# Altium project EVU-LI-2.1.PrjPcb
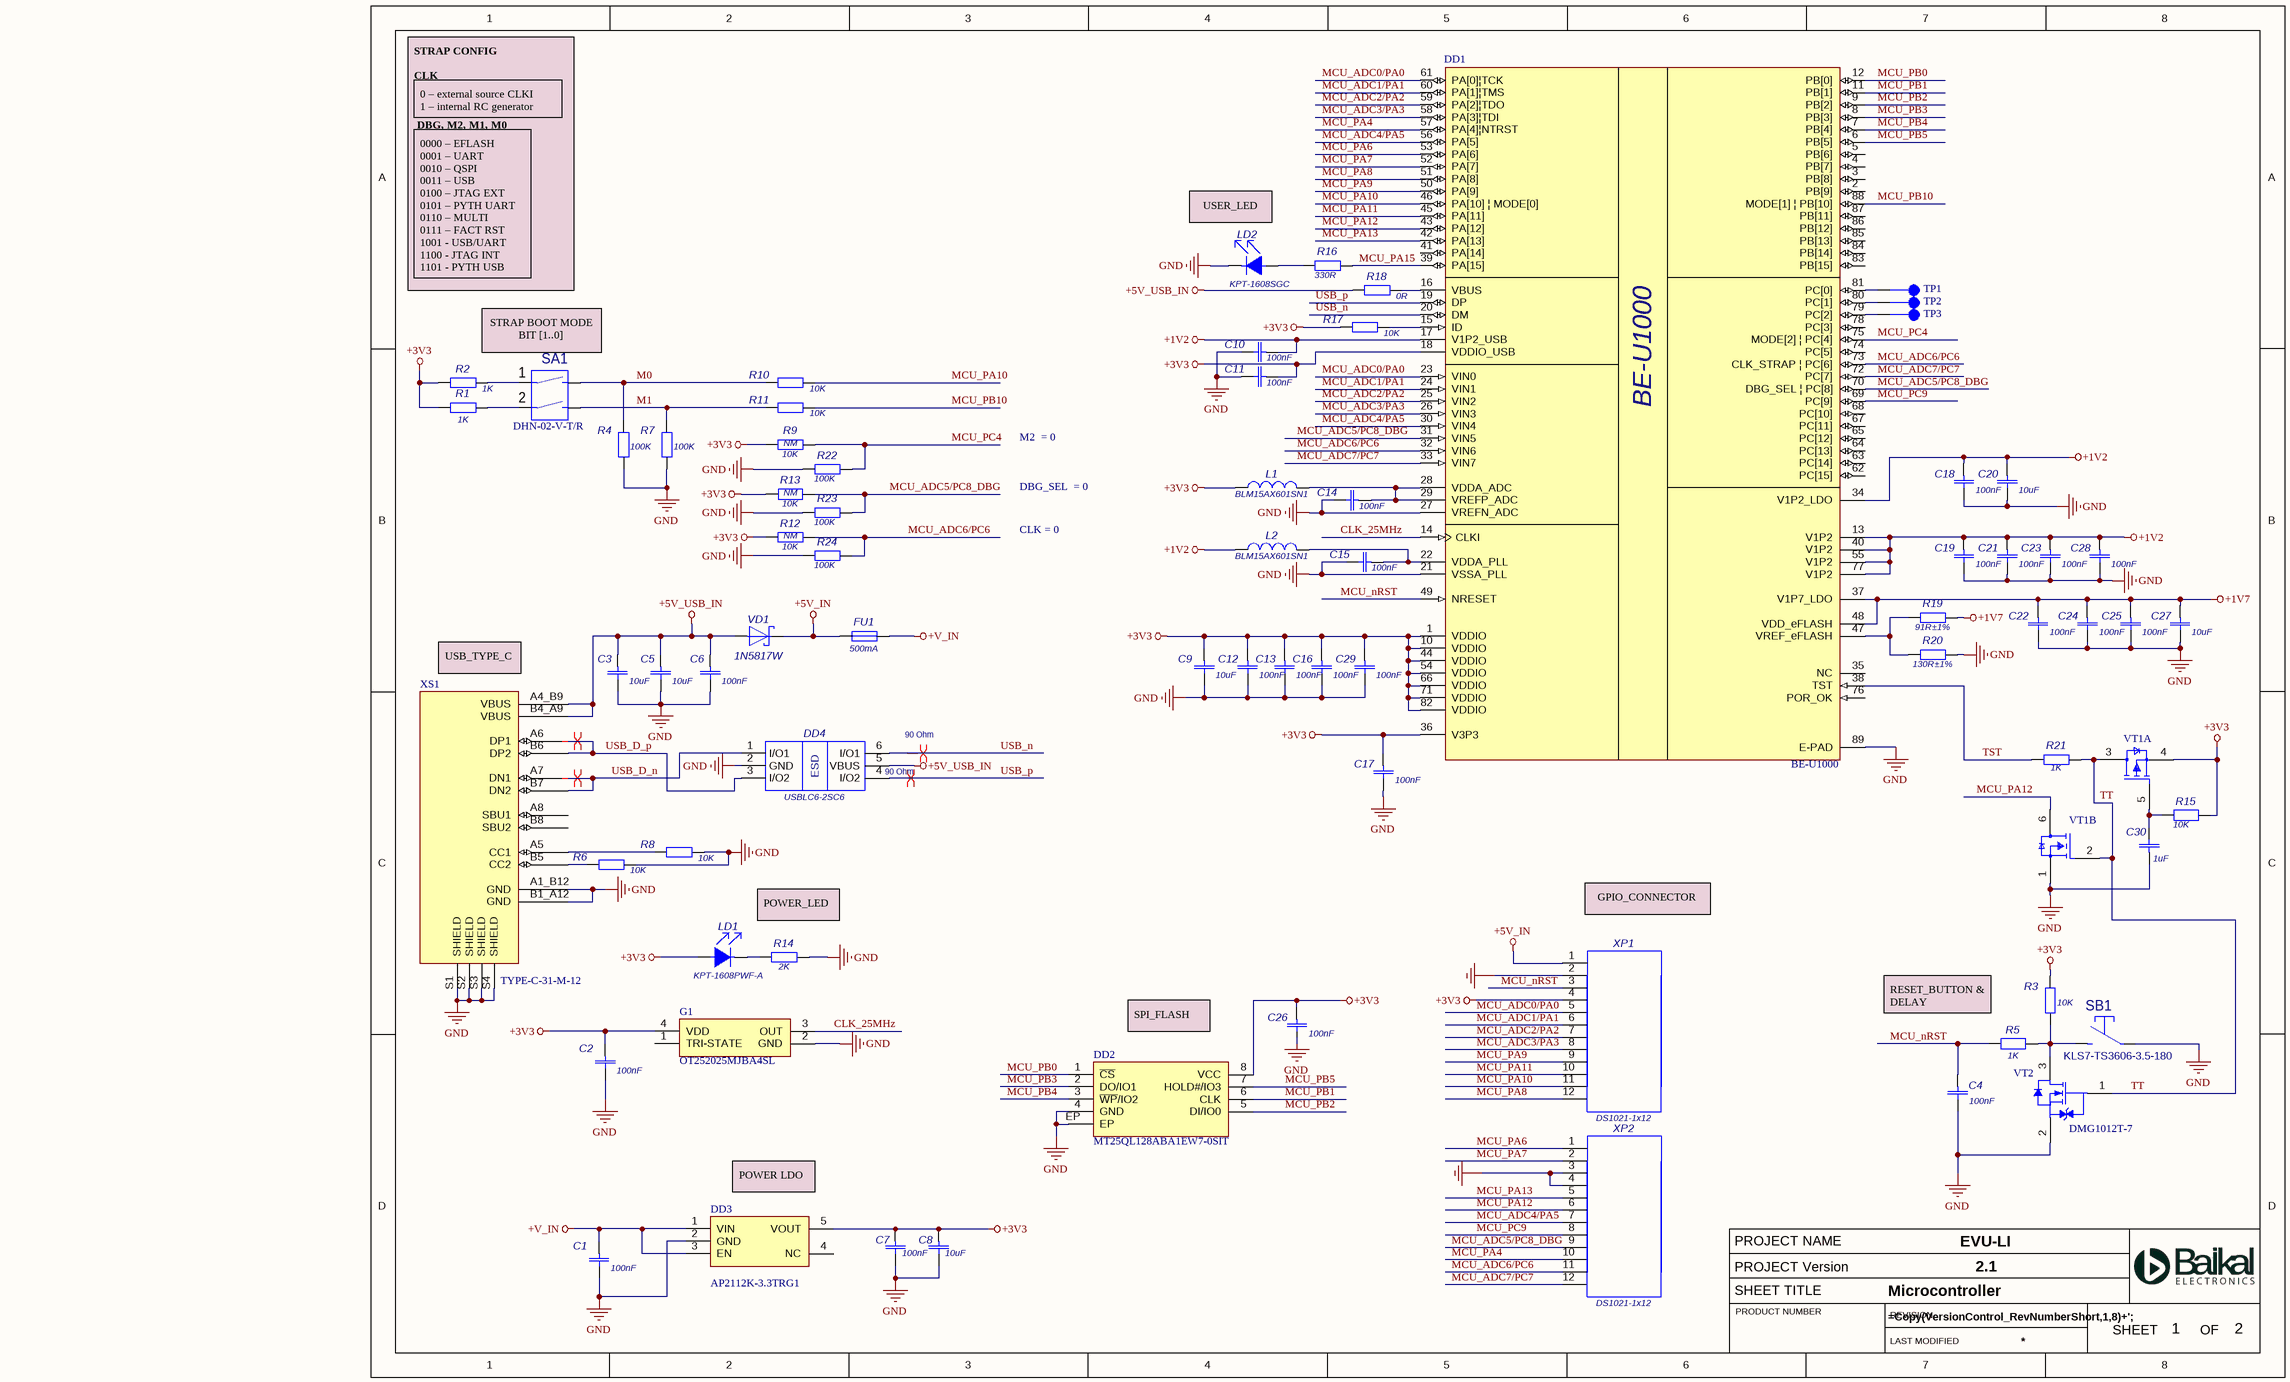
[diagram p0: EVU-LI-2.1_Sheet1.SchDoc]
2 sheets, 75 parts. Net scope: global (net labels, ports and power ports of the same name join across sheets).
Board file: PCB_EVU-LI_2.1.PcbDoc
Sheets:
  EVU-LI-2.1_Sheet1.SchDoc
  EVU-LI-2.1_Sheet2.SchDoc

## Sheet EVU-LI-2.1_Sheet1.SchDoc: EVU-LI-2.1
size A3; SheetNumber: 1; SheetTotal: 2; Prj: EVU-LI; Ver: 2.1; Ti: Microcontroller

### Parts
C1  value 100nF  [CAPC1005X50N]  (hidden comment: GRM155R71C104KA88D)
C2  value 100nF  [CAPC1005X50N]  (hidden comment: GRM155R71C104KA88D)
C3  value 10uF  [CAPC2012X125N]  (hidden comment: GRM21BR61C106KE15L)
C4  value 100nF  [CAPC1005X50N]  (hidden comment: GRM155R71C104KA88D)
C5  value 10uF  [CAPC2012X125N]  (hidden comment: GRM21BR61C106KE15L)
C6  value 100nF  [CAPC1005X50N]  (hidden comment: GRM155R71C104KA88D)
C7  value 100nF  [CAPC1005X50N]  (hidden comment: GRM155R71C104KA88D)
C8  value 10uF  [CAPC2012X125N]  (hidden comment: GRM21BR61C106KE15L)
C9  value 10uF  [CAPC2012X125N]  (hidden comment: GRM21BR61C106KE15L)
C10  value 100nF  [CAPC1005X50N]  (hidden comment: GRM155R71C104KA88D)
C11  value 100nF  [CAPC1005X50N]  (hidden comment: GRM155R71C104KA88D)
C12  value 100nF  [CAPC1005X50N]  (hidden comment: GRM155R71C104KA88D)
C13  value 100nF  [CAPC1005X50N]  (hidden comment: GRM155R71C104KA88D)
C14  value 100nF  [CAPC1005X50N]  (hidden comment: GRM155R71C104KA88D)
C15  value 100nF  [CAPC1005X50N]  (hidden comment: GRM155R71C104KA88D)
C16  value 100nF  [CAPC1005X50N]  (hidden comment: GRM155R71C104KA88D)
C17  value 100nF  [CAPC1005X50N]  (hidden comment: GRM155R71C104KA88D)
C18  value 100nF  [CAPC1005X50N]  (hidden comment: GRM155R71C104KA88D)
C19  value 100nF  [CAPC1005X50N]  (hidden comment: GRM155R71C104KA88D)
C20  value 10uF  [CAPC2012X125N]  (hidden comment: GRM21BR61C106KE15L)
C21  value 100nF  [CAPC1005X50N]  (hidden comment: GRM155R71C104KA88D)
C22  value 100nF  [CAPC1005X50N]  (hidden comment: GRM155R71C104KA88D)
C23  value 100nF  [CAPC1005X50N]  (hidden comment: GRM155R71C104KA88D)
C24  value 100nF  [CAPC1005X50N]  (hidden comment: GRM155R71C104KA88D)
C25  value 100nF  [CAPC1005X50N]  (hidden comment: GRM155R71C104KA88D)
C26  value 100nF  [CAPC1005X50N]  (hidden comment: GRM155R71C104KA88D)
C27  value 10uF  [CAPC2012X125N]  (hidden comment: GRM21BR61C106KE15L)
C28  value 100nF  [CAPC1005X50N]  (hidden comment: GRM155R71C104KA88D)
C29  value 100nF  [CAPC1005X50N]  (hidden comment: GRM155R71C104KA88D)
C30  value 1uF  [CAPC1005X50N]  (hidden comment: GRM155Z71A105KE01D)
DD1  BE-U1000  [QFNWB10X10-88L-AL]
DD2  MT25QL128ABA1EW7-0SIT  [W-PDFN-8(5x6)]
DD3  AP2112K-3.3TRG1  [SOT95P285X140-5N]
DD4  USBLC6-2SC6  [SOT95P280X145-6N]
FU1  value 500mA  [RESC1608X45N]  (hidden comment: JFC0603-0500FS)
G1  OT252025MJBA4SL  [Crystal_4-SMD_2.5x2.0]
L1  BLM15AX601SN1  [BLM15X10X05X50N]
L2  BLM15AX601SN1  [BLM15X10X05X50N]
LD1  KPT-1608PWF-A  [KPT1608X16X08X75N_LINE]
LD2  KPT-1608SGC  [KPT1608X16X08X75N_LINE]
R1  value 1K  [RESC1005X35N]  (hidden comment: RC0402FR-071KL)
R2  value 1K  [RESC1005X35N]  (hidden comment: RC0402FR-071KL)
R3  value 10K  [RESC1005X35N]  (hidden comment: RC0402FR-0710KL)
R4  value 100K  [RESC1005X35N]  (hidden comment: RC0402FR-07100KL)
R5  value 1K  [RESC1005X35N]  (hidden comment: RC0402FR-071KL)
R6  value 10K  [RESC1005X35N]  (hidden comment: RC0402FR-0710KL)
R7  value 100K  [RESC1005X35N]  (hidden comment: RC0402FR-07100KL)
R8  value 10K  [RESC1005X35N]  (hidden comment: RC0402FR-0710KL)
R9  value 10K  DNP: NM  [RESC1005X35N]  (hidden comment: RC0402FR-0710KL)
R10  value 10K  [RESC1005X35N]  (hidden comment: RC0402FR-0710KL)
R11  value 10K  [RESC1005X35N]  (hidden comment: RC0402FR-0710KL)
R12  value 10K  DNP: NM  [RESC1005X35N]  (hidden comment: RC0402FR-0710KL)
R13  value 10K  DNP: NM  [RESC1005X35N]  (hidden comment: RC0402FR-0710KL)
R14  value 2K  [RESC1005X35N]  (hidden comment: CR0402-JW-202-G)
R15  value 10K  [RESC1005X35N]  (hidden comment: RC0402FR-0710KL)
R16  value 330R  [RESC1005X35N]  (hidden comment: CR0402-JW-331-G)
R17  value 10K  [RESC1005X35N]  (hidden comment: RC0402FR-0710KL)
R18  value 0R  [RESC1005X35N]  (hidden comment: RC0402FR-070RL)
R19  value 91R  Tolerance: ±1%  [RESC1005X35N]  (hidden comment: RC0402FR-0791RL)
R20  value 130R  Tolerance: ±1%  [RESC1005X35N]  (hidden comment: RC0402FR-07130RL)
R21  value 1K  [RESC1005X35N]  (hidden comment: RC0402FR-071KL)
R22  value 100K  [RESC1005X35N]  (hidden comment: RC0402FR-07100KL)
R23  value 100K  [RESC1005X35N]  (hidden comment: RC0402FR-07100KL)
R24  value 100K  [RESC1005X35N]  (hidden comment: RC0402FR-07100KL)
SA1  DHN-02-V-T/R  [A6H-21]
SB1  KLS7-TS3606-3.5-180  [KLS7-TS3606-3.5-180]
TP1  (no value)  [PIN_0.7x0.7]  (no BOM)
TP2  (no value)  [PIN_0.7x0.7]  (no BOM)
TP3  (no value)  [PIN_0.7x0.7]  (no BOM)
VD1  1N5817W  [DIOD_SOD-123]
VT1  BSS8402DW-7-F  [FP-SOT363-MFG]  (value not drawn)  (parts A,B of 2)
VT2  DMG1012T-7  [DIOD-SOT523-3_V]
XP1  DS1021-1x12  [PLS-12]
XP2  DS1021-1x12  [PLS-12]
XS1  TYPE-C-31-M-12  [TYPE-C-31-M-12]

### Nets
+1V2: C10.2 C18.2 C19.2 C20.2 C21.2 C23.2 C28.2 DD1.13(V1P2) DD1.17(V1P2_USB) DD1.34(V1P2_LDO) DD1.40(V1P2) DD1.55(V1P2) DD1.77(V1P2) L2.1
+1V7: C22.2 C24.2 C25.2 C27.2 DD1.37(V1P7_LDO) DD1.48(VDD_eFLASH) R19.2
+3V3: C2.2 C7.2 C8.2 C9.2 C11.2 C12.2 C13.2 C16.2 C17.2 C26.2 C29.2 DD1.1(VDDIO) DD1.10(VDDIO) DD1.18(VDDIO_USB) DD1.36(V3P3) DD1.44(VDDIO) DD1.54(VDDIO) DD1.66(VDDIO) DD1.71(VDDIO) DD1.82(VDDIO) DD2.8(VCC) DD3.5(VOUT) G1.4(VDD) L1.1 LD1.1 R1.1 R2.1 R3.2 R9.1 R12.1 R13.2 R15.1 R17.1 VT1.4(S2) XP1.4
+5V_IN: FU1.1 VD1.C XP1.1
+5V_USB_IN: C3.2 C5.2 C6.2 DD4.5(VBUS) R18.1 VD1.A XS1.A4_B9(VBUS) XS1.B4_A9(VBUS)
+V_IN: C1.2 DD3.1(VIN) DD3.3(EN) FU1.2
GND: C1.1 C2.1 C3.1 C4.1 C5.1 C6.1 C7.1 C8.1 C9.1 C10.1 C11.1 C12.1 C13.1 C14.1 C15.1 C16.1 C17.1 C18.1 C19.1 C20.1 C21.1 C22.1 C23.1 C24.1 C25.1 C26.1 C27.1 C28.1 C29.1 C30.2 DD1.21(VSSA_PLL) DD1.27(VREFN_ADC) DD1.89(E-PAD) DD2.4(GND) DD2.EP DD3.2(GND) DD4.2(GND) G1.2(GND) LD2.2 R4.1 R6.2 R7.1 R8.2 R14.2 R20.2 R22.1 R23.1 R24.1 SB1.1 VT1.1(S1) VT2.2(S) XP1.2 XP2.3 XP2.4 XS1.A1_B12(GND) XS1.B1_A12(GND) XS1.S1(SHIELD) XS1.S2(SHIELD) XS1.S3(SHIELD) XS1.S4(SHIELD)
CLK_25MHz: DD1.14(CLKI) G1.3(OUT)
M0: R4.2 R10.1 SA1.11
M1: R7.2 R11.1 SA1.22
MCU_ADC0/PA0: DD1.23(VIN0) DD1.61(PA[0]¦TCK) XP1.5
MCU_ADC1/PA1: DD1.24(VIN1) DD1.60(PA[1]¦TMS) XP1.6
MCU_ADC2/PA2: DD1.25(VIN2) DD1.59(PA[2]¦TDO) XP1.7
MCU_ADC3/PA3: DD1.26(VIN3) DD1.58(PA[3]¦TDI) XP1.8
MCU_ADC4/PA5: DD1.30(VIN4) DD1.56(PA[5]) XP2.7
MCU_ADC5/PC8_DBG: DD1.31(VIN5) DD1.70(DBG_SEL_¦_PC[8]) R13.1 R23.2 XP2.9
MCU_ADC6/PC6: DD1.32(VIN6) DD1.73(CLK_STRAP_¦_PC[6]) R12.2 R24.2 XP2.11
MCU_ADC7/PC7: DD1.33(VIN7) DD1.72(PC[7]) XP2.12
MCU_nRST: C4.2 DD1.49(NRESET) R5.2 XP1.3
MCU_PA4: DD1.57(PA[4]¦NTRST) XP2.10
MCU_PA6: DD1.53(PA[6]) XP2.1
MCU_PA7: DD1.52(PA[7]) XP2.2
MCU_PA8: DD1.51(PA[8]) XP1.12
MCU_PA9: DD1.50(PA[9]) XP1.9
MCU_PA10: DD1.46(PA[10]_¦_MODE[0]) R10.2 XP1.11
MCU_PA11: DD1.45(PA[11]) XP1.10
MCU_PA12: DD1.43(PA[12]) VT1.6(D1) XP2.6
MCU_PA13: DD1.42(PA[13]) XP2.5
MCU_PA15: DD1.39(PA[15]) R16.2
MCU_PB0: DD1.12(PB[0]) DD2.1(~{CS})
MCU_PB1: DD1.11(PB[1]) DD2.6(CLK)
MCU_PB2: DD1.9(PB[2]) DD2.5(DI/IO0)
MCU_PB3: DD1.8(PB[3]) DD2.2(DO/IO1)
MCU_PB4: DD1.7(PB[4]) DD2.3(~{WP}/IO2)
MCU_PB5: DD1.6(PB[5]) DD2.7(HOLD#/IO3)
MCU_PB10: DD1.88(MODE[1]_¦_PB[10]) R11.2
MCU_PC4: DD1.75(MODE[2]_¦_PC[4]) R9.2 R22.2
MCU_PC9: DD1.69(PC[9]) XP2.8
TST: DD1.38(TST) R21.1
TT: R21.2 VT1.2(G1) VT1.3(D2) VT2.1(G)
USB_D_n: DD4.1(I/O1) XS1.A7(DN1) XS1.B7(DN2)
USB_D_p: DD4.3(I/O2) XS1.A6(DP1) XS1.B6(DP2)
USB_n: DD1.20(DM) DD4.6(I/O1)
USB_p: DD1.19(DP) DD4.4(I/O2)
NetC14_2: C14.2 DD1.28(VDDA_ADC) DD1.29(VREFP_ADC) L1.2
NetC15_2: C15.2 DD1.22(VDDA_PLL) L2.2
NetC30_1: C30.1 R15.2 VT1.5(G2)
NetDD1_15: DD1.15(ID) R17.2
NetDD1_16: DD1.16(VBUS) R18.2
NetDD1_47: DD1.47(VREF_eFLASH) R19.1 R20.1
NetDD1_79: DD1.79(PC[2]) TP2.1
NetDD1_80: DD1.80(PC[1]) TP3.1
NetDD1_81: DD1.81(PC[0]) TP1.1
NetLD1_2: LD1.2 R14.1
NetLD2_1: LD2.1 R16.1
NetR1_2: R1.2 SA1.2
NetR2_2: R2.2 SA1.1
NetR3_1: R3.1 R5.1 SB1.2 VT2.3(D)
NetR6_1: R6.1 XS1.B5(CC2)
NetR8_1: R8.1 XS1.A5(CC1)

Not connected (* = marked no-connect by the designer): DD1 2(PB[9]) 3(PB[8]) 4(PB[7]) 5(PB[6]) 35(NC) 41(PA[14]) 62(PC[15]) 63(PC[14]) 64(PC[13]) 65(PC[12]) 67(PC[11]) 68(PC[10]) 74(PC[5]) 76(POR_OK) 78(PC[3]) 83(PB[15]) 84(PB[14]) 85(PB[13]) 86(PB[12]) 87(PB[11]); DD3 4(NC); G1 1(TRI-STATE); XS1 A8(SBU1) B8(SBU2)

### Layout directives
differential pair: (no net found under the mark)
differential pair; USB_HS_90: 90 Ohm; differential pair class 90 Ohm: USB_n, USB_p

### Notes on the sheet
- 0 – external source CLKI
  1 – internal RC generator
- USER_LED
- STRAP CONFIG
  CLK
  DBG, M2, M1, M0
- 0000 – EFLASH
  0001 – UART
  0010 – QSPI
  0011 – USB
  0100 – JTAG EXT
  0101 – PYTH UART
  0110 – MULTI
  0111 – FACT RST
  1001 - USB/UART
  1100 - JTAG INT
  1101 - PYTH USB
- STRAP BOOT MODE BIT [1..0]
- M2  = 0
- DBG_SEL  = 0
- CLK = 0
- (near XS1) USB_TYPE_C
- GPIO_CONNECTOR
- POWER_LED
- (near DD2) SPI_FLASH
- (near R5) RESET_BUTTON & DELAY
- (near DD3) POWER LDO

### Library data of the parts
C1 C2 C4 C6 C7 C10-C19 C21-C26 C28 C29 = GRM155R71C104KA88D: 0402 X7R  0,1 uF±10% 16V; Manufacturer: "Murata"; Tolerance: ±10%; Power_Voltage: 16В; NOM: 0402 X7R 100nF ±10% 16В; Value Ru: 0,1 мкФ
C3 C5 C8 C9 C20 C27 = GRM21BR61C106KE15L: 0805 X5R 10uF±10% 16V; Manufacturer: "Murata"; Tolerance: ±10%; Value Ru: 10 мкФ
C30 = GRM155Z71A105KE01D: 0402 X7R  1 uF±10% 10V; Manufacturer: "Murata"; Tolerance: ±10%; Power_Voltage: 10В; NOM: 0402 X7R 1uF ±10% 10В; Value Ru: 1 мкФ
DD1 = BE-U1000: Microcontroller BE-U1000; Manufacturer: "Baikal Electronics"; TKE: QFN 88
DD2 = MT25QL128ABA1EW7-0SIT: FLASH 128MBIT SPI 8WPDFN; Manufacturer: "Micron"
DD3 = AP2112K-3.3TRG1: LDO voltage regulator; Manufacturer_Name: Diodes Incorporated; Manufacturer: "Diodes"
DD4 = USBLC6-2SC6: Very low capacitance ESD protector; Manufacturer: "STMicroelectronics"; MARK: UL26
FU1 = JFC0603-0500FS: Fuse 500mA 32V 0603; Manufacturer: "JDT Fuse Industrial"; MARK: F
G1 = OT252025MJBA4SL: 3.3V ±10ppm 5mA ±20ppm CMOS 25MHz  Oscillator; Manufacturer: "YXC"; Manufacturer_Part_Number: OT322525MJBA4SL; TKE: SMD3225-4P
L1 L2 = BLM15AX601SN1: 600 Ohms/100MHz 0,5A 0,34 Ohms; Manufacturer: "Murata"; Value: 600 Ом/100MГц 0,5A 0,34 Ом
LD1 = KPT-1608PWF-A: 0603 LED Diod SMD White; Manufacturer: "Kingbright"; TKE: 0603
LD2 = KPT-1608SGC: 0603 LED Diod SMD Green; Manufacturer: "Kingbright"; TKE: 0603
R1 R2 R5 = RC0402FR-071KL: 0402 1 kOhm ±1% 0.063W; Manufacturer: "Yageo"; Power_Voltage: 0,0625 W; MARK: 102; TKE: 0402; NOM: 0402 1K ±1% 0,0625 W; Value Ru: 1 кОм
R3 R6 R8-R13 R17 = RC0402FR-0710KL: 0402 10 kOhm ±1% 0.063W; Manufacturer: "Yageo"; Power_Voltage: 0,0625 W; MARK: 103; TKE: 0402; NOM: 0402 10K ±1% 0,0625 W; Value Ru: 10 кОм
R4 R7 R22-R24 = RC0402FR-07100KL: 0402 100 kOhm ±1% 0.063W; Manufacturer: "Yageo"; Power_Voltage: 0,0625 W; MARK: 103; TKE: 0402; NOM: 0402 100K ±1% 0,0625 W; Value Ru: 100 кОм
R14 = CR0402-JW-202-G: 0402 2 kOhm±5% 0.063W; Manufacturer: "Bourns"; Power_Voltage: 0,0625 W; MARK: 202; TKE: 0402; NOM: 0402 2K ±5% 0,0625 W; Tolerance: ±5%; Value Ru: 2 кОм
R15 = RC0402FR-0710KL: 0402 10 kOhm ±1% 0.063W; Manufacturer: "Yageo"; TKE: 0402; MARK: 103; Power_Voltage: 0,0625 W; NOM: 0402 10K ±1% 0,0625 W; Value Ru: 10 кОм
R16 = CR0402-JW-331-G: 0402 330 Ohm±5% 0.063W; Manufacturer: "Bourns"; Power_Voltage: 0,0625 W; MARK: 331; TKE: 0402; NOM: 0402 330R ±5% 0,0625 W; Tolerance: ±5%; Value Ru: 330 Ом
R18 = RC0402FR-070RL: 0402 0 Ohm ±1% 0.063W; Manufacturer: "Yageo"; Power_Voltage: 0,0625 W; MARK: 000; TKE: 0402; NOM: 0402 0R ±1% 0,0625 W; Value Ru: 0 Ом
R19 = RC0402FR-0791RL: 0402 91 Ohm ±1% 0.063W; Manufacturer: "Yageo"; Power_Voltage: 0,0625 W; MARK: 102; TKE: 0402; NOM: 0402 91R ±1% 0,0625 W; Value Ru: 91 Ом
R20 = RC0402FR-07130RL: 0402 130 Ohm ±1% 0.063W; Manufacturer: "Yageo"; Power_Voltage: 0,0625 W; MARK: 102; TKE: 0402; NOM: 0402 130R ±1% 0,0625 W; Value Ru: 130 Ом
R21 = RC0402FR-071KL: 0402 1 kOhm ±1% 0.063W; Manufacturer: "Yageo"; TKE: 0402; MARK: 102; Power_Voltage: 0,0625 W; NOM: 0402 1K ±1% 0,0625 W; Value Ru: 1 кОм
SA1 = DHN-02-V-T/R: 2 switches in case; Manufacturer: "DIPTRONICS"; ESKDname: Переключатель DHN-02-V-T/R
SB1 = KLS7-TS3606-3.5-180: Kind of Tactile Switch; Manufacturer: "KLS"; ESKDname: Кнопка тактовая KLS7-TS3606-3.5-180
TP1-TP3 = TP: Contacts, Test points and mounting hole pin
VD1 = 1N5817W: Diode Schottky 20V 1A [SOD-123]; Manufacturer: HOTTECH ELECTRONICS; ESKDname: * 1N5817W, *
VT1 = BSS8402DW-7-F: MOSFET N/P-CH 60V/50V SC70-6; Manufacturer: Diodes; Drain To Source Voltage: 60/-50V; Threshold Vgs Max: 2.5/-2V; Number Of Channels: 2; Turn On Delay Time: 7/10ns; Turn Off Delay Time: 11/18ns; Depletion Mode: False; Number Of P Channels: 1; Transconductance: 0.08/0.05S; Rthja Max: 625°C/W; Gate To Source Voltage: 20V; Power Dissipation: 200mW; Drain To Source Resistance: 4.4/10Ω; Continuous Drain Current: 115/-130mA; Threshold Vgs Min: 1/-0.8V; Max Junction Temp: +150°C; Automotive Grade: NA; Drain To Source Breakdown Voltage: 70/-50V; Standoff Height: 0mm; Pulse Drain Current: 800mA
VT2 = DMG1012T-7: N-Channel Enhancement Mode MOSFET, 20 V, 630 mA, -55 to 150 degC, 3-Pin SOT23, RoHS, Tape and Reel; Manufacturer: Diodes Inc; Continuous Drain Current (ID): 630mA; Number of Channels: 1; Drain to Source Voltage (Vdss): 20V; Gate to Source Voltage (Vgs): 6V; Turn-On Delay Time: 5.1ns; Rds On Max: 400mOhm; Power Dissipation: 280mW; Fall Time: 12.3ns; Input Capacitance: 60.67pF; Turn-Off Delay Time: 26.7ns; Rise Time: 7.4ns; Drain to Source Resistance: 300mOhm; Element Configuration: Single; Case\/Package: SOT-523; Threshold Voltage: 1V
XP1 XP2 = DS1021-1x12: Connector 2.54 pitch, 1 rows, 8.54 height; ManufacturerPartNumber: DS1021-1x12 (PLS-12); Manufacturer: "Connfly"
XS1 = TYPE-C-31-M-12: USB TYPE-C 5A 16P Female SMD USB Connectors; Manufacturer: "GCT"; MP: USB4800-03-A; MF: Global Connector Technology

## Sheet EVU-LI-2.1_Sheet2.SchDoc
size A3; SheetNumber: 2; SheetTotal: 2; Prj: EVU-LI; Ver: 2.1; Ti: Revision History
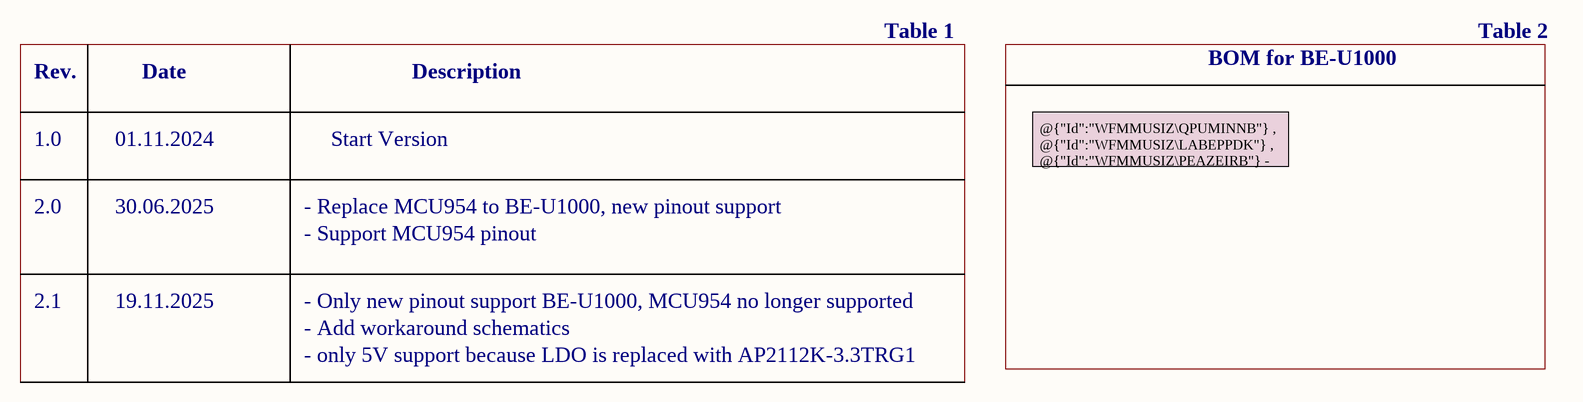
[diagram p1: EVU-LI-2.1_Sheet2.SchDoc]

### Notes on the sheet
- Table 1
- BOM for BE-U1000
- Table 2
- Rev.
- Date
- Description
- 1.0
- 01.11.2024
- Start Version
- @{"Id":"WFMMUSIZ\QPUMINNB"} , @{"Id":"WFMMUSIZ\LABEPPDK"} , @{"Id":"WFMMUSIZ\PEAZEIRB"} -  NOT MOUNT
- 2.0
- 30.06.2025
- - Replace MCU954 to BE-U1000, new pinout support
- - Support MCU954 pinout
- 2.1
- 19.11.2025
- - Only new pinout support BE-U1000, MCU954 no longer supported
- - Add workaround schematics
- - only 5V support because LDO is replaced with AP2112K-3.3TRG1

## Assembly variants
EVU-LI-2.1: not fitted R9 R12 R13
